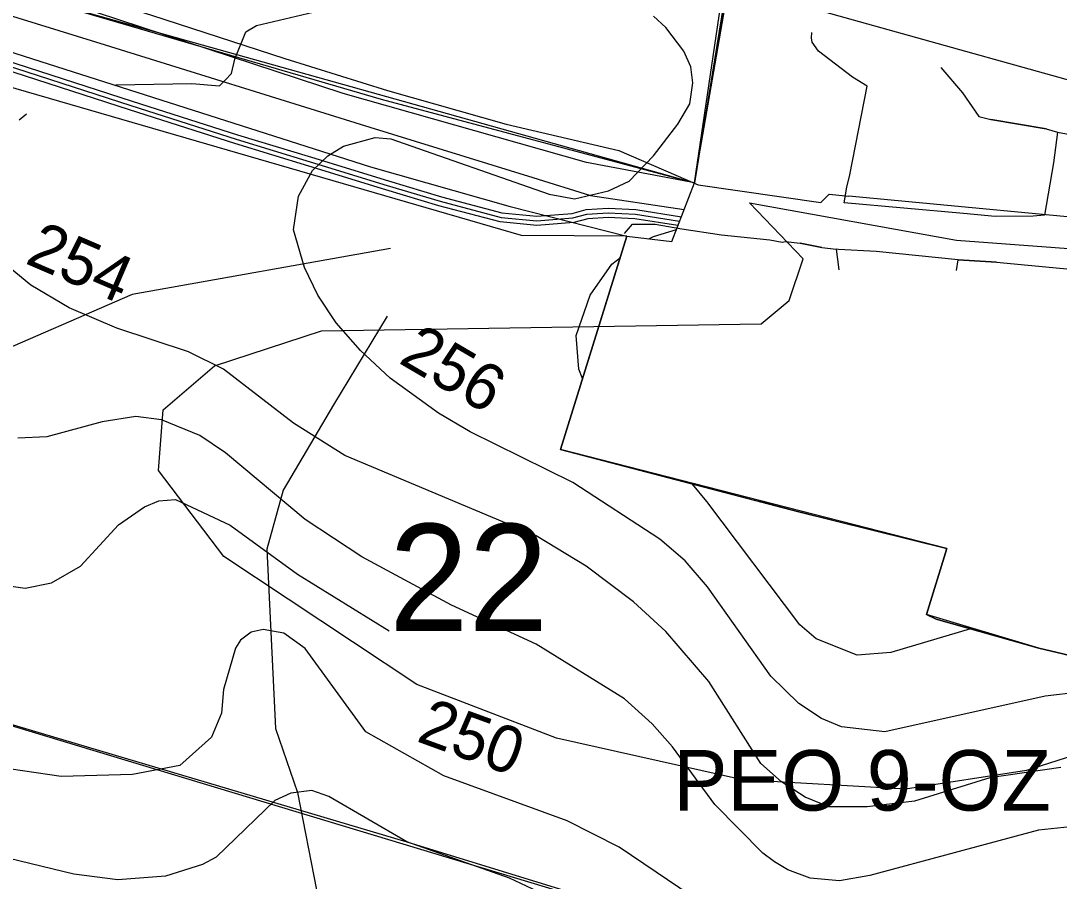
# Model space of a CAD drawing. Extents: x -662500 to -653478, y -1056827 to -1049993.
# Drawn here: x -660694.1 to -660470.9, y -1052282.8 to -1052097.9 of the extents above; entities that cross this region are included whole.
import ezdxf

# ---------------------------------------------------------------- set-up
doc = ezdxf.new("R2010")
doc.units = 0
for name, color, linetype in [('63LINIE', 7, 'Continuous'), ('Vrstva 1', 7, 'Continuous'), ('Vrstva 20', 7, 'Continuous'), ('Vrstva 22', 7, 'Continuous'), ('Vrstva 24', 7, 'Continuous'), ('Vrstva 42', 7, 'Continuous'), ('Vrstva 45', 7, 'Continuous'), ('Vrstva 47', 7, 'Continuous'), ('Vrstva 5', 7, 'Continuous'), ('Vrstva 57', 7, 'Continuous'), ('Vrstva 6', 7, 'Continuous'), ('Vrstva 7', 7, 'Continuous')]:
    doc.layers.add(name, color=color, linetype=linetype)

msp = doc.modelspace()

# ---------------------------------------------------------------- linework, layer by layer
at = {"layer": '63LINIE'}
msp.add_lwpolyline([(-661089.92, -1052023.41), (-661033.05, -1052031.56), (-660920.35, -1052046.48), (-660821, -1052060.23), (-660803.07, -1052062.71), (-660768.57, -1052074.37), (-660678.06, -1052102.44), (-660619.13, -1052120.72), (-660584.07, -1052131.59), (-660571.71, -1052135.42), (-660551.54, -1052138.42)], dxfattribs=at)
at = {"layer": 'Vrstva 1'}
for points in [[(-660554.23, -1052145.33), (-660549.33, -1052132.73), (-660543.74, -1052100.07), (-660537.55, -1052064.32), (-660536.99, -1052061.08), (-660533.42, -1052042.18), (-660529.4, -1052017.99), (-660526.37, -1052016.17), (-660497.13, -1051998.48), (-660473.03, -1051983.91), (-660444.41, -1051966.62), (-660443.04, -1051941.53), (-660409.35, -1051945.41), (-660388.98, -1051947.77), (-660362.03, -1051950.34), (-660358.34, -1051950.81), (-660318.47, -1051954.21), (-660286.74, -1051956.91), (-660259.81, -1051958.85), (-660255.56, -1051959.16), (-660215.66, -1051962.04), (-660216.74, -1051952.44), (-660214.33, -1051927.93), (-660170.69, -1051923.36)], [(-660495.07, -1052211.29), (-660517.03, -1052205.91), (-660527.17, -1052203.32), (-660534.27, -1052201.47), (-660536.66, -1052200.85), (-660578.14, -1052190.03), (-660572.16, -1052170.84), (-660563.85, -1052144.19), (-660554.23, -1052145.33)], [(-660408.77, -1052283.62), (-660402.29, -1052259.33), (-660394.65, -1052237.63), (-660389.99, -1052217.3), (-660396.18, -1052215.3), (-660414.84, -1052209.49), (-660417.67, -1052208.59), (-660421.03, -1052221.2), (-660427.21, -1052239.6), (-660428.58, -1052243.68), (-660452.47, -1052238.38), (-660475.36, -1052232.69), (-660497.36, -1052226.43)], [(-660497.36, -1052226.43), (-660499.48, -1052225.45), (-660495.07, -1052211.29)]]:
    msp.add_lwpolyline(points, dxfattribs=at)
at = {"layer": 'Vrstva 20'}
for points in [[(-660693, -1052092.39), (-660549.33, -1052132.73), (-660529.4, -1052017.99), (-660444.65, -1051966.93), (-660443.04, -1051941.53), (-660507.57, -1051940.01), (-660528.33, -1051935.72), (-660624.47, -1051996.3), (-660674.23, -1052051.96)], [(-660611.17, -1052274.32), (-660487.99, -1052312.15), (-660486.82, -1052314.01), (-660462.36, -1052329.02), (-660459.17, -1052336.8), (-660433.93, -1052352.12), (-660408.77, -1052283.62), (-660402.29, -1052259.33), (-660394.65, -1052237.63), (-660389.99, -1052217.3), (-660417.67, -1052208.59), (-660428.58, -1052243.68), (-660475.36, -1052232.69), (-660499.48, -1052225.45), (-660495.07, -1052211.29), (-660578.14, -1052190.03), (-660563.85, -1052144.19), (-660586.5, -1052144.05), (-660704.06, -1052109.9), (-660743.35, -1052235.04)]]:
    msp.add_lwpolyline(points, close=True, dxfattribs=at)
at = {"layer": 'Vrstva 22'}
msp.add_lwpolyline([(-661110.22, -1052170.21), (-661096.01, -1052128.52), (-660487.99, -1052312.15), (-660506.09, -1052352.23)], close=True, dxfattribs=at)
at = {"layer": 'Vrstva 24'}
for points in [[(-660328, -1052135), (-660352, -1052135.5), (-660451.5, -1052115.5), (-660661, -1052057), (-660695, -1052042.5), (-660723, -1052024.5), (-660747.5, -1052000), (-660756.5, -1051991), (-660777.56, -1051972.71)], [(-660320.5, -1052262.5), (-660379.5, -1052252), (-660417.5, -1052245), (-660451.5, -1052250.5), (-660478, -1052259), (-660504, -1052263), (-660539, -1052261), (-660579, -1052252), (-660609, -1052240.5), (-660650.5, -1052213), (-660664.5, -1052194.5), (-660663.5, -1052181.5), (-660652.5, -1052172), (-660629.5, -1052164.5), (-660535, -1052163), (-660529, -1052158), (-660526, -1052149), (-660537.5, -1052137), (-660493, -1052145), (-660399.5, -1052152), (-660376, -1052150.5), (-660358, -1052148), (-660341.5, -1052142)]]:
    msp.add_lwpolyline(points, dxfattribs=at)
at = {"layer": 'Vrstva 42'}
msp.add_line((-660572.44, -1052139.42), (-660567.9, -1052139.12), dxfattribs=at)
for points in [[(-660806.43, -1052073.46), (-660805.97, -1052073.55), (-660786.17, -1052078.32), (-660768.37, -1052083.66), (-660748.27, -1052090.89), (-660690.41, -1052109.64), (-660670.47, -1052116.09), (-660647.85, -1052123.31), (-660631.93, -1052128.18), (-660615.37, -1052133.26), (-660603.98, -1052136.67), (-660590.91, -1052140.12), (-660583.21, -1052140.84), (-660575.46, -1052140.25), (-660572.44, -1052139.42)], [(-660567.9, -1052139.12), (-660562.03, -1052139.45), (-660552.53, -1052140.95)]]:
    msp.add_lwpolyline(points, dxfattribs=at)
at = {"layer": 'Vrstva 45'}
for p, q in [((-660524.2, -1052101.58), (-660524.1, -1052100.38)), ((-660524.2, -1052101.58), (-660524.1, -1052100.38)), ((-660473.76, -1052121.12), (-660485.62, -1052119.1)), ((-660473.76, -1052121.12), (-660485.62, -1052119.1)), ((-660471.3, -1052121.8), (-660459.7, -1052124.03)), ((-660471.3, -1052121.8), (-660459.7, -1052124.03)), ((-660476.51, -1052139.83), (-660484.74, -1052139.9)), ((-660476.51, -1052139.83), (-660484.74, -1052139.9)), ((-660521.94, -1052146.63), (-660526.61, -1052145.69)), ((-660521.94, -1052146.63), (-660526.61, -1052145.69)), ((-660518.89, -1052146.94), (-660518.34, -1052151.37)), ((-660518.89, -1052146.94), (-660518.34, -1052151.37)), ((-660510.29, -1052147.47), (-660518.36, -1052147.04)), ((-660510.29, -1052147.47), (-660518.36, -1052147.04)), ((-660492.99, -1052151.55), (-660492.67, -1052149.21)), ((-660492.99, -1052151.55), (-660492.67, -1052149.21)), ((-660484.44, -1052149.72), (-660492.67, -1052149.21)), ((-660484.44, -1052149.72), (-660492.67, -1052149.21))]:
    msp.add_line(p, q, dxfattribs=at)
for points in [[(-660830.25, -1052048.16), (-660801.6, -1052052.43), (-660785.76, -1052056.82), (-660749.53, -1052069.14), (-660722.87, -1052078.18), (-660694.73, -1052087.6), (-660666.02, -1052096.71), (-660637.38, -1052105.99), (-660615.28, -1052112.88), (-660589.8, -1052120.12), (-660565.6, -1052125.72)], [(-660830.25, -1052048.16), (-660801.6, -1052052.43), (-660785.76, -1052056.82), (-660749.53, -1052069.14), (-660722.87, -1052078.18), (-660694.73, -1052087.6), (-660666.02, -1052096.71), (-660637.38, -1052105.99), (-660615.28, -1052112.88), (-660589.8, -1052120.12), (-660565.6, -1052125.72)], [(-660471.3, -1052121.8), (-660472.2, -1052128.41), (-660474.12, -1052139.64), (-660476.51, -1052139.83), (-660484.74, -1052139.9), (-660491.54, -1052139.28), (-660517.15, -1052136.97), (-660516.61, -1052133.65), (-660515.96, -1052130.96), (-660512.22, -1052111.92), (-660515.37, -1052109.98), (-660522.67, -1052104.41), (-660524.04, -1052102.47), (-660524.2, -1052101.58)], [(-660471.3, -1052121.8), (-660472.2, -1052128.41), (-660474.12, -1052139.64), (-660476.51, -1052139.83), (-660484.74, -1052139.9), (-660491.54, -1052139.28), (-660517.15, -1052136.97), (-660516.61, -1052133.65), (-660515.96, -1052130.96), (-660512.22, -1052111.92), (-660515.37, -1052109.98), (-660522.67, -1052104.41), (-660524.04, -1052102.47), (-660524.2, -1052101.58)], [(-660496.42, -1052107.92), (-660491.71, -1052113.37), (-660488.23, -1052118.46), (-660485.62, -1052119.1), (-660473.76, -1052121.12), (-660471.3, -1052121.8)], [(-660496.42, -1052107.92), (-660491.71, -1052113.37), (-660488.23, -1052118.46), (-660485.62, -1052119.1), (-660473.76, -1052121.12), (-660471.3, -1052121.8)], [(-660565.6, -1052125.72), (-660548.55, -1052133.15), (-660522.21, -1052136.92), (-660520.4, -1052135.15), (-660516.13, -1052135.6)], [(-660565.6, -1052125.72), (-660548.55, -1052133.15), (-660522.21, -1052136.92), (-660520.4, -1052135.15), (-660516.13, -1052135.6)], [(-660450.08, -1052141.84), (-660451.03, -1052141.75), (-660516.13, -1052135.6)], [(-660450.08, -1052141.84), (-660451.03, -1052141.75), (-660516.13, -1052135.6)], [(-660564.37, -1052143.61), (-660562.65, -1052141.61), (-660557.78, -1052141.59), (-660552.06, -1052142.58), (-660543.55, -1052143.9), (-660533.12, -1052144.98), (-660530.51, -1052145.48), (-660529.78, -1052145.27), (-660526.61, -1052145.69), (-660521.94, -1052146.63), (-660518.89, -1052146.94)], [(-660564.37, -1052143.61), (-660562.65, -1052141.61), (-660557.78, -1052141.59), (-660552.06, -1052142.58), (-660543.55, -1052143.9), (-660533.12, -1052144.98), (-660530.51, -1052145.48), (-660529.78, -1052145.27), (-660526.61, -1052145.69), (-660521.94, -1052146.63), (-660518.89, -1052146.94)], [(-660492.67, -1052149.21), (-660510.29, -1052147.47), (-660518.36, -1052147.04), (-660518.89, -1052146.94)], [(-660492.67, -1052149.21), (-660510.29, -1052147.47), (-660518.36, -1052147.04), (-660518.89, -1052146.94)], [(-660492.67, -1052149.21), (-660484.44, -1052149.72), (-660464.01, -1052151.68)], [(-660492.67, -1052149.21), (-660484.44, -1052149.72), (-660464.01, -1052151.68)]]:
    msp.add_lwpolyline(points, dxfattribs=at)
at = {"layer": 'Vrstva 47'}
for points in [[(-660747.95, -1052089.94), (-660690.1, -1052108.69), (-660670.16, -1052115.14), (-660647.55, -1052122.36), (-660631.64, -1052127.22), (-660615.08, -1052132.3), (-660603.71, -1052135.7), (-660590.73, -1052139.13), (-660583.2, -1052139.84), (-660575.63, -1052139.26), (-660572.61, -1052138.43), (-660567.9, -1052138.11), (-660561.92, -1052138.46), (-660552.15, -1052139.99)], [(-660552.9, -1052141.9), (-660562.13, -1052140.45), (-660567.89, -1052140.12), (-660572.28, -1052140.41), (-660575.29, -1052141.24), (-660583.22, -1052141.85), (-660591.09, -1052141.11), (-660604.25, -1052137.63), (-660615.66, -1052134.22), (-660632.22, -1052129.14), (-660648.14, -1052124.27), (-660670.78, -1052117.04), (-660690.71, -1052110.59), (-660748.59, -1052091.84)]]:
    msp.add_lwpolyline(points, dxfattribs=at)
at = {"layer": 'Vrstva 5'}
for points in [[(-660415.51, -1051792.48), (-660387.33, -1051842.39), (-660368.51, -1051881.97), (-660363.96, -1051894.27), (-660362.05, -1051903.98), (-660361.48, -1051911.34), (-660361.47, -1051915.93), (-660361.97, -1051944.48), (-660362.03, -1051950.34), (-660388.98, -1051947.77), (-660443.04, -1051941.53), (-660444.41, -1051966.62), (-660473.03, -1051983.91), (-660497.13, -1051998.48), (-660529.4, -1052017.99), (-660533.42, -1052042.18), (-660542.09, -1052088.13), (-660549.33, -1052132.73), (-660572.52, -1052128.33), (-660624.87, -1052113.48), (-660745.13, -1052073.98)], [(-660757.57, -1052084.94), (-660618.97, -1052129.25), (-660588.97, -1052137.76), (-660563.85, -1052144.19), (-660554.23, -1052145.33), (-660549.33, -1052132.73), (-660572.52, -1052128.33), (-660624.87, -1052113.48), (-660745.13, -1052073.98)], [(-660757.57, -1052084.94), (-660618.97, -1052129.25), (-660588.97, -1052137.76), (-660563.85, -1052144.19), (-660578.14, -1052190.03), (-660527.17, -1052203.32), (-660495.07, -1052211.29), (-660499.48, -1052225.45), (-660497.36, -1052226.43), (-660475.36, -1052232.69), (-660428.58, -1052243.68), (-660421.03, -1052221.2), (-660417.67, -1052208.59), (-660396.18, -1052215.3), (-660389.99, -1052217.3), (-660394.65, -1052237.63), (-660402.29, -1052259.33), (-660408.77, -1052283.62)]]:
    msp.add_lwpolyline(points, dxfattribs=at)
at = {"layer": 'Vrstva 57'}
for points in [[(-660614.7, -1052146.79), (-660670.16, -1052156.66), (-660702.59, -1052170.76), (-660725.62, -1052188.62), (-660759.45, -1052215.88), (-660863.32, -1052358.75)], [(-660615.41, -1052161.36), (-660626.92, -1052180.39), (-660637.73, -1052198.72), (-660641.26, -1052211.41), (-660639.38, -1052249.95), (-660634.68, -1052263.7), (-660630.57, -1052284.61), (-660627.61, -1052306.06), (-660626.81, -1052332.78), (-660627.04, -1052339.48), (-660634.33, -1052360.39), (-660644.19, -1052384.83), (-660659.7, -1052407.15), (-660752.84, -1052470.52)]]:
    msp.add_lwpolyline(points, dxfattribs=at)
at = {"layer": 'Vrstva 6'}
msp.add_lwpolyline([(-660717.09, -1051942.16), (-660678.48, -1051976.85), (-660636.23, -1052006.19), (-660634.2, -1052007.19), (-660674.23, -1052051.96), (-660693, -1052092.39), (-660616.69, -1052114.74), (-660549.33, -1052132.73), (-660535.03, -1052035.66), (-660529.4, -1052017.99), (-660444.79, -1051966.85), (-660443.04, -1051941.53), (-660507.57, -1051940.01), (-660528.33, -1051935.72), (-660624.47, -1051996.3), (-660625.14, -1051997.08), (-660628.82, -1051995.51), (-660670.4, -1051966.64), (-660708.78, -1051932.15)], dxfattribs=at)
msp.add_lwpolyline([(-660462.36, -1052329.02), (-660459.17, -1052336.8), (-660433.93, -1052352.12), (-660409.6, -1052285.62), (-660402.29, -1052259.33), (-660394.65, -1052237.63), (-660389.99, -1052217.3), (-660417.67, -1052208.59), (-660421.03, -1052221.2), (-660428.58, -1052243.68), (-660452.47, -1052238.38), (-660475.36, -1052232.69), (-660499.48, -1052225.45), (-660495.07, -1052211.29), (-660578.14, -1052190.03), (-660563.85, -1052144.19), (-660586.5, -1052144.05), (-660704.06, -1052109.9), (-660743.35, -1052235.04), (-661096.01, -1052128.52), (-661110.22, -1052170.21), (-660506.09, -1052352.23), (-660487.99, -1052312.15)], close=True, dxfattribs=at)
at = {"layer": 'Vrstva 7'}
for p, q in [((-660643.48, -1052098.87), (-660631.29, -1052096.04)), ((-660555.47, -1052099.3), (-660558.17, -1052096.89)), ((-660648.16, -1052106.1), (-660645.75, -1052100.29)), ((-660645.75, -1052100.29), (-660643.48, -1052098.87)), ((-660551.65, -1052104.4), (-660555.47, -1052099.3)), ((-660550.09, -1052107.8), (-660551.65, -1052104.4)), ((-660648.88, -1052109.24), (-660648.16, -1052106.1)), ((-660650.2, -1052110.62), (-660648.88, -1052109.24)), ((-660549.66, -1052111.2), (-660550.09, -1052107.8)), ((-660673.67, -1052111.66), (-660657.37, -1052111.34)), ((-660657.37, -1052111.34), (-660651.42, -1052111.84)), ((-660651.42, -1052111.84), (-660650.2, -1052110.62)), ((-660550.37, -1052115.74), (-660549.66, -1052111.2)), ((-660552.92, -1052120.13), (-660550.37, -1052115.74)), ((-660694.5, -1052119.14), (-660692.94, -1052117.84)), ((-660558.14, -1052126.93), (-660552.92, -1052120.13)), ((-660628.17, -1052126.93), (-660624.77, -1052124.8)), ((-660624.77, -1052124.8), (-660617.97, -1052122.96)), ((-660617.97, -1052122.96), (-660614.57, -1052123.25)), ((-660614.57, -1052123.25), (-660580.56, -1052135.15)), ((-660631.43, -1052130.05), (-660628.17, -1052126.93)), ((-660563.41, -1052132.32), (-660558.14, -1052126.93)), ((-660634.41, -1052135.57), (-660631.43, -1052130.05)), ((-660567.8, -1052134.44), (-660563.41, -1052132.32)), ((-660635.54, -1052142.8), (-660634.41, -1052135.57)), ((-660580.56, -1052135.15), (-660575.1, -1052136.14)), ((-660575.1, -1052136.14), (-660567.8, -1052134.44)), ((-660558.17, -1052144.22), (-660553.22, -1052142.74)), ((-660633.13, -1052150.88), (-660635.54, -1052142.8)), ((-660559.12, -1052144.75), (-660558.17, -1052144.22)), ((-660567.09, -1052150.17), (-660565.26, -1052148.72)), ((-660691.95, -1052154.71), (-660697.61, -1052150.03)), ((-660630.3, -1052156.83), (-660633.13, -1052150.88)), ((-660571.77, -1052156.83), (-660567.09, -1052150.17)), ((-660683.73, -1052159.53), (-660691.95, -1052154.71)), ((-660626.33, -1052162.78), (-660630.3, -1052156.83)), ((-660574.75, -1052165.48), (-660571.77, -1052156.83)), ((-660673.52, -1052163.92), (-660683.73, -1052159.53)), ((-660621.09, -1052168.74), (-660626.33, -1052162.78)), ((-660658.08, -1052169.02), (-660673.52, -1052163.92)), ((-660574.18, -1052172.71), (-660574.75, -1052165.48)), ((-660650.57, -1052172.71), (-660658.08, -1052169.02)), ((-660614.71, -1052174.69), (-660621.09, -1052168.74)), ((-660635.54, -1052184.33), (-660650.57, -1052172.71)), ((-660573.38, -1052174.76), (-660574.18, -1052172.71)), ((-660604.36, -1052182.2), (-660614.71, -1052174.69)), ((-660669.41, -1052182.91), (-660676.64, -1052184.04)), ((-660663.89, -1052183.62), (-660669.41, -1052182.91)), ((-660597.56, -1052186.17), (-660604.36, -1052182.2)), ((-660676.64, -1052184.04), (-660688.55, -1052187.3)), ((-660655.67, -1052187.02), (-660663.89, -1052183.62)), ((-660624.49, -1052191.27), (-660635.54, -1052184.33)), ((-660688.55, -1052187.3), (-660694.78, -1052187.59)), ((-660650.14, -1052190.7), (-660655.67, -1052187.02)), ((-660575.45, -1052197.08), (-660597.56, -1052186.17)), ((-660632.99, -1052205.02), (-660650.14, -1052190.7)), ((-660583.39, -1052208.56), (-660624.49, -1052191.27)), ((-660556.75, -1052209.27), (-660575.45, -1052197.08)), ((-660546.69, -1052201.19), (-660549.74, -1052197.44)), ((-660664.45, -1052201.05), (-660660.91, -1052200.77)), ((-660660.91, -1052200.77), (-660649.15, -1052206.29)), ((-660673.1, -1052206.15), (-660667.57, -1052202.32)), ((-660667.57, -1052202.32), (-660664.45, -1052201.05)), ((-660526.7, -1052227.69), (-660546.69, -1052201.19)), ((-660620.8, -1052213.09), (-660632.99, -1052205.02)), ((-660681.32, -1052215.08), (-660673.1, -1052206.15)), ((-660649.15, -1052206.29), (-660634.69, -1052216.78)), ((-660572.62, -1052215.08), (-660583.39, -1052208.56)), ((-660551.36, -1052213.95), (-660556.75, -1052209.27)), ((-660601.53, -1052223.44), (-660620.8, -1052213.09)), ((-660546.54, -1052219.47), (-660551.36, -1052213.95)), ((-660687.55, -1052218.62), (-660681.32, -1052215.08)), ((-660562.42, -1052222.73), (-660572.62, -1052215.08)), ((-660713.49, -1052216.92), (-660693.22, -1052219.76)), ((-660693.22, -1052219.76), (-660687.55, -1052218.62)), ((-660634.69, -1052216.78), (-660614.99, -1052228.97)), ((-660532.92, -1052238.69), (-660546.54, -1052219.47)), ((-660555.47, -1052229.11), (-660562.42, -1052222.73)), ((-660583.39, -1052231.8), (-660601.53, -1052223.44)), ((-660644.61, -1052229.25), (-660646.88, -1052230.95)), ((-660642.06, -1052228.68), (-660644.61, -1052229.25)), ((-660637.58, -1052229.48), (-660642.06, -1052228.68)), ((-660632.99, -1052232.79), (-660637.58, -1052229.48)), ((-660546.26, -1052239.88), (-660555.47, -1052229.11)), ((-660523.16, -1052230.67), (-660526.7, -1052227.69)), ((-660489.98, -1052228.53), (-660507.15, -1052233.64)), ((-660646.88, -1052230.95), (-660648.01, -1052232.65)), ((-660564.4, -1052243.56), (-660583.39, -1052231.8)), ((-660514.35, -1052234.17), (-660523.16, -1052230.67)), ((-660648.01, -1052232.65), (-660650.56, -1052241.58)), ((-660619.95, -1052250.65), (-660632.99, -1052232.79)), ((-660507.15, -1052233.64), (-660514.35, -1052234.17)), ((-660526.94, -1052244.56), (-660532.92, -1052238.69)), ((-660535.07, -1052257.45), (-660546.26, -1052239.88)), ((-660650.56, -1052241.58), (-660650.99, -1052246.68)), ((-660473.99, -1052243), (-660508.42, -1052250.65)), ((-660466.62, -1052242.15), (-660473.99, -1052243)), ((-660558.45, -1052248.95), (-660564.4, -1052243.56)), ((-660522.05, -1052247.76), (-660526.94, -1052244.56)), ((-660650.99, -1052246.68), (-660653.11, -1052251.78)), ((-660554.06, -1052253.91), (-660558.45, -1052248.95)), ((-660517.72, -1052249.58), (-660522.05, -1052247.76)), ((-660508.42, -1052250.65), (-660517.72, -1052249.58)), ((-660653.11, -1052251.78), (-660659.92, -1052257.88)), ((-660603.23, -1052260.14), (-660619.95, -1052250.65)), ((-660544.99, -1052266.24), (-660554.06, -1052253.91)), ((-660685.43, -1052260.29), (-660700.73, -1052258.02)), ((-660659.92, -1052257.88), (-660670.12, -1052259.86)), ((-660530.67, -1052261.42), (-660535.07, -1052257.45)), ((-660470.58, -1052258.3), (-660485.89, -1052260.57)), ((-660670.12, -1052259.86), (-660685.43, -1052260.29)), ((-660576.73, -1052269.78), (-660603.23, -1052260.14)), ((-660485.89, -1052260.57), (-660502.05, -1052265.53)), ((-660631.58, -1052263.26), (-660636.11, -1052263.83)), ((-660627.89, -1052264.54), (-660631.58, -1052263.26)), ((-660525.57, -1052264.68), (-660530.67, -1052261.42)), ((-660639.51, -1052265.39), (-660652.12, -1052277.58)), ((-660636.11, -1052263.83), (-660639.51, -1052265.39)), ((-660611.17, -1052274.32), (-660627.89, -1052264.54)), ((-660520.47, -1052266.8), (-660525.57, -1052264.68)), ((-660534.64, -1052276.73), (-660544.99, -1052266.24)), ((-660512.25, -1052266.8), (-660520.47, -1052266.8)), ((-660502.05, -1052265.53), (-660512.25, -1052266.8)), ((-660565.54, -1052275.45), (-660576.73, -1052269.78)), ((-660475.4, -1052271.77), (-660511.68, -1052281.54)), ((-660464.07, -1052270.63), (-660475.4, -1052271.77)), ((-660589.06, -1052282.11), (-660611.17, -1052274.32)), ((-660534.21, -1052296.56), (-660565.54, -1052275.45)), ((-660682.73, -1052281.26), (-660696.62, -1052277.86)), ((-660652.12, -1052277.58), (-660655.1, -1052279.13)), ((-660532.14, -1052278.6), (-660534.64, -1052276.73)), ((-660529.3, -1052280.34), (-660532.14, -1052278.6)), ((-660655.1, -1052279.13), (-660663.04, -1052281.69)), ((-660524.44, -1052282.11), (-660529.3, -1052280.34)), ((-660673.31, -1052282.46), (-660682.73, -1052281.26)), ((-660663.04, -1052281.69), (-660673.31, -1052282.46)), ((-660575.45, -1052288.49), (-660589.06, -1052282.11)), ((-660518.2, -1052282.68), (-660524.44, -1052282.11)), ((-660511.68, -1052281.54), (-660518.2, -1052282.68))]:
    msp.add_line(p, q, dxfattribs=at)

# ---------------------------------------------------------------- texts
at = {"layer": 'Vrstva 20'}
msp.add_text('PEO 9-OZ', height=13, dxfattribs=at).set_placement((-660553.86, -1052267.58))
at = {"layer": 'Vrstva 57'}
msp.add_text('22', height=23, dxfattribs=at).set_placement((-660614.99, -1052228.97))
at = {"layer": 'Vrstva 7'}
for s, rotation, p in [('254', 336.7052, (-660693.47, -1052149.89)), ('256', 329.7425, (-660613.2, -1052171.25)), ('250', 340.0164, (-660609.34, -1052252.6))]:
    msp.add_text(s, height=10, rotation=rotation, dxfattribs=at).set_placement(p)

doc.saveas('drawing.dxf')
